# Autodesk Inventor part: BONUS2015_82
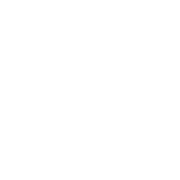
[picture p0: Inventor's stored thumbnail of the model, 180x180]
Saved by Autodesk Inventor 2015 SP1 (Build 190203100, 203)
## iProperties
Created: 2015-05
Part Number: BONUS2015_82
Material: Generisch
Document SubType Name: Modeling
Density: 1 g/cm^3
Appearance: Vorgabe
xx: 82
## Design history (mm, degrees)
